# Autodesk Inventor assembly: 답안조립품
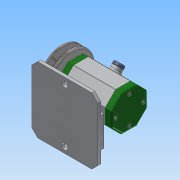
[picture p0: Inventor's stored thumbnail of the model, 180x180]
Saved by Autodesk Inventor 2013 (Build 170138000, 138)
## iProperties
Created: 2018-06
Part Number: 답안조립품
Document SubType Name: Assembly
Designer: Administrator
Author: Administrator
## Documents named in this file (16)
- C:\Users\Administrator\Desktop\480608V1011\답안조립품.iam
- C:\Users\Administrator\Desktop\480608V1011\V벨트풀리.ipt
- C:\Users\Administrator\Desktop\480608V1011\고무캡.ipt
- C:\Users\Administrator\Desktop\480608V1011\너트 M8.ipt
- 너트 M8.ipt
- C:\Users\Administrator\Desktop\480608V1011\뒤커버.ipt
- C:\Users\Administrator\Desktop\480608V1011\베어링 15x32x9.ipt
- C:\Users\Administrator\Desktop\480608V1011\본체.ipt
- C:\Users\Administrator\Desktop\480608V1011\볼트 M4x12.ipt
- C:\Users\Administrator\Desktop\480608V1011\스프링와셔 8.ipt
- C:\Users\Administrator\Desktop\480608V1011\앞커버.ipt
- C:\Users\Administrator\Desktop\480608V1011\오일 실 15 25 7.ipt
- C:\Users\Administrator\Desktop\480608V1011\와셔 8x17.ipt
- C:\Users\Administrator\Desktop\480608V1011\축.ipt
- C:\Users\Administrator\Desktop\480608V1011\키 3x3x12.ipt
- 키 3x3x12.ipt
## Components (2 placed, 2 different names)
1. V벨트풀리:1
2. 고무캡:1 — 각도:1
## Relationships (1: Angle 1)
- 각도:1 [Angle]: 고무캡:1
